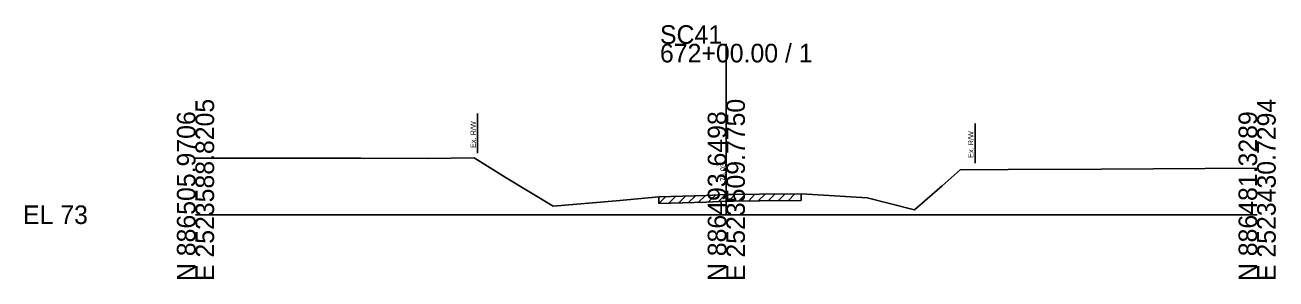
# Model space of a CAD drawing. Extents: x -26 to 183, y -10 to 24021.
# Drawn here: x -25.7 to 162.8, y 4490.3 to 4528.6 of the extents above; entities that cross this region are included whole.
import ezdxf

# ---------------------------------------------------------------- set-up
doc = ezdxf.new("R2010")
doc.units = 0
for name, color, linetype in [('RD_GPK_XS_Cell', 7, 'Continuous'), ('RD_XS_ExGround', 7, 'Continuous'), ('RD_XS_ExPaveRet', 7, 'Continuous'), ('RD_XS_ExRW', 7, 'Continuous'), ('RD_XS_TX_Elev_EX', 7, 'Continuous')]:
    doc.layers.add(name, color=color, linetype=linetype)

msp = doc.modelspace()

# ---------------------------------------------------------------- linework, layer by layer
at = {"layer": 'RD_GPK_XS_Cell'}
for p, q in [((80, 4500), (80, 4525.78)), ((0, 4500), (80, 4500)), ((80, 4500), (160, 4500))]:
    msp.add_line(p, q, dxfattribs=at)
at = {"layer": 'RD_XS_ExGround'}
for p, q in [((0, 4508.53), (24.92, 4508.51)), ((24.92, 4508.51), (35.05, 4508.48)), ((35.05, 4508.48), (41.99, 4508.59)), ((41.99, 4508.59), (46.8, 4505.57)), ((112.52, 4504.36), (115.26, 4506.76)), ((115.26, 4506.76), (122.5, 4506.82)), ((122.5, 4506.82), (136.49, 4506.89)), ((136.49, 4506.89), (160, 4507.02)), ((46.8, 4505.57), (53.89, 4501.3)), ((108.35, 4500.76), (112.52, 4504.36)), ((63.42, 4502.11), (69.82, 4502.68)), ((69.82, 4502.68), (76.98, 4502.92)), ((76.98, 4502.92), (80, 4503.03)), ((80, 4503.03), (81.08, 4503.06)), ((81.08, 4503.06), (85.02, 4503.08)), ((85.02, 4503.08), (91.26, 4503.13)), ((91.26, 4503.13), (95.48, 4502.9)), ((95.48, 4502.9), (101.25, 4502.55)), ((101.25, 4502.55), (104.4, 4501.75)), ((53.89, 4501.3), (63.42, 4502.11)), ((104.4, 4501.75), (108.35, 4500.76))]:
    msp.add_line(p, q, dxfattribs=at)
at = {"layer": 'RD_XS_ExPaveRet'}
for p, q in [((69.82, 4501.68), (70.85, 4502.72)), ((69.82, 4501.68), (69.82, 4502.68)), ((71.32, 4501.73), (72.35, 4502.77)), ((72.82, 4501.78), (73.85, 4502.82)), ((74.32, 4501.83), (75.35, 4502.87)), ((75.82, 4501.88), (76.85, 4502.92)), ((77.32, 4501.93), (78.35, 4502.97)), ((78.82, 4501.99), (79.85, 4503.02)), ((80.32, 4502.04), (81.35, 4503.06)), ((81.82, 4502.07), (82.82, 4503.07)), ((83.32, 4502.07), (84.32, 4503.08)), ((84.82, 4502.08), (85.83, 4503.09)), ((86.32, 4502.09), (87.33, 4503.1)), ((87.82, 4502.11), (88.83, 4503.11)), ((89.32, 4502.12), (90.33, 4503.13)), ((91.26, 4503.13), (91.26, 4502.13)), ((69.82, 4501.68), (76.98, 4501.92)), ((76.98, 4501.92), (80, 4502.03)), ((80, 4502.03), (81.08, 4502.06)), ((81.08, 4502.06), (85.02, 4502.08)), ((85.02, 4502.08), (91.26, 4502.13))]:
    msp.add_line(p, q, dxfattribs=at)
at = {"layer": 'RD_XS_ExRW'}
for p, q in [((42.5, 4515.27), (42.5, 4509.27)), ((117.5, 4513.78), (117.5, 4507.78))]:
    msp.add_line(p, q, dxfattribs=at)

# ---------------------------------------------------------------- texts
at = {"layer": 'RD_GPK_XS_Cell'}
for s, p in [('SC41', (70, 4525.78)), ('672+00.00 / 1', (70, 4522.98)), ('EL 73', (-26, 4498.6))]:
    msp.add_text(s, height=2.8, dxfattribs=at).set_placement(p)
for s, p in [('E 2523588.8205', (2.8, 4490)), ('E 2523509.7750', (82.8, 4490)), ('E 2523430.7294', (162.8, 4490)), ('N 886505.9706', (0, 4490)), ('N 886493.6498', (80, 4490)), ('N 886481.3289', (160, 4490))]:
    msp.add_text(s, height=2.8, rotation=90, dxfattribs=at).set_placement(p)
at = {"layer": 'RD_XS_ExRW'}
for p in [(42.25, 4510.06), (117.25, 4508.57)]:
    msp.add_text('Ex. R/W ', height=0.8, rotation=90, dxfattribs=at).set_placement(p)
at = {"layer": 'RD_XS_TX_Elev_EX'}
msp.add_text('76.03', height=0.8, rotation=90, dxfattribs=at).set_placement((79.9, 4505.03))

doc.saveas('drawing.dxf')
